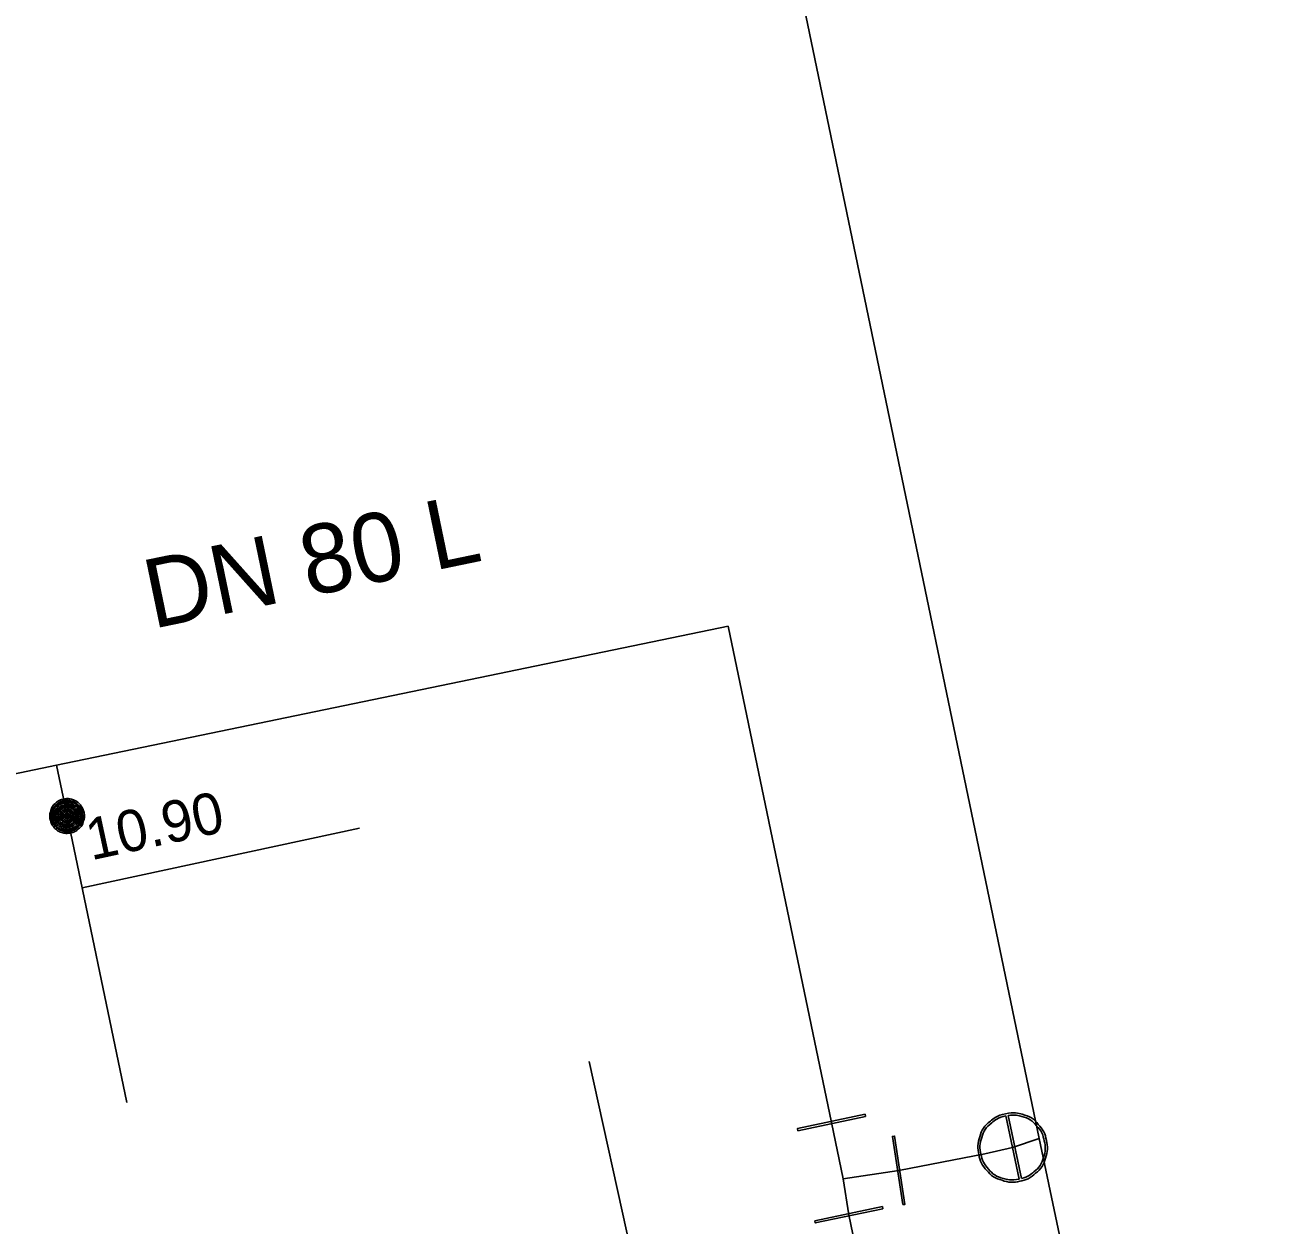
# Model space of a CAD drawing. Extents: x -820257 to -819974, y -1070894 to -1070484.
# Drawn here: x -820221.68 to -820185.49, y -1070586.44 to -1070551.67 of the extents above; entities that cross this region are included whole.
import ezdxf

# ---------------------------------------------------------------- set-up
doc = ezdxf.new("R2010")
doc.units = 0
for name, color, linetype in [('Oměrka vodovodu', 7, 'Continuous'), ('Oměrka-text', 7, 'Continuous'), ('Pás-šoupě', 7, 'Continuous'), ('Přípojka vodovodu', 7, 'Continuous'), ('Přípojkový uzávěr', 7, 'Continuous'), ('Roz-řad', 7, 'Continuous'), ('Roz-řad-popis základní', 7, 'Continuous'), ('Řad-šoupě', 7, 'Continuous')]:
    doc.layers.add(name, color=color, linetype=linetype)

msp = doc.modelspace()

# ---------------------------------------------------------------- linework, layer by layer
at = {"layer": 'Oměrka vodovodu'}
for p, q in [((-820220.023, -1070576.676), (-820211.991, -1070574.942)), ((-820199.277, -1070609.167), (-820205.332, -1070581.705))]:
    msp.add_line(p, q, dxfattribs=at)
at = {"layer": 'Pás-šoupě'}
for points in [[(-820192.875, -1070585.113), (-820193.262, -1070583.278)], [(-820193.2, -1070583.267), (-820192.814, -1070585.098)]]:
    msp.add_lwpolyline(points, dxfattribs=at)
for points in [[(-820193.274, -1070583.217), (-820193.027, -1070583.165), (-820192.767, -1070583.241), (-820192.506, -1070583.318), (-820192.324, -1070583.526), (-820192.142, -1070583.733), (-820192.088, -1070583.989), (-820192.034, -1070584.243), (-820192.114, -1070584.503), (-820192.194, -1070584.763), (-820192.4, -1070584.941), (-820192.606, -1070585.12), (-820192.861, -1070585.174), (-820193.114, -1070585.227), (-820193.374, -1070585.147), (-820193.635, -1070585.068), (-820193.813, -1070584.862), (-820193.991, -1070584.657), (-820194.045, -1070584.402), (-820194.099, -1070584.146), (-820194.017, -1070583.883), (-820193.935, -1070583.62), (-820193.728, -1070583.444), (-820193.521, -1070583.269), (-820193.274, -1070583.217)], [(-820192.814, -1070585.098), (-820192.609, -1070585.041), (-820192.441, -1070584.894), (-820192.248, -1070584.727), (-820192.173, -1070584.484), (-820192.098, -1070584.241), (-820192.149, -1070584.002), (-820192.2, -1070583.761), (-820192.371, -1070583.567), (-820192.542, -1070583.374), (-820192.786, -1070583.301), (-820192.998, -1070583.238), (-820193.2, -1070583.267)], [(-820193.262, -1070583.278), (-820193.492, -1070583.327), (-820193.687, -1070583.492), (-820193.882, -1070583.656), (-820193.958, -1070583.903), (-820194.034, -1070584.149), (-820193.983, -1070584.39), (-820193.933, -1070584.628), (-820193.766, -1070584.82), (-820193.599, -1070585.012), (-820193.355, -1070585.087), (-820193.112, -1070585.163), (-820192.875, -1070585.113)]]:
    msp.add_open_spline(points, degree=3, dxfattribs=at)
at = {"layer": 'Přípojka vodovodu'}
msp.add_lwpolyline([(-820220.764, -1070573.123), (-820220.458, -1070574.591), (-820218.725, -1070582.897)], dxfattribs=at)
at = {"layer": 'Přípojkový uzávěr'}
for points in [[(-820219.968, -1070574.489), (-820219.942, -1070574.612), (-820219.981, -1070574.742), (-820220.02, -1070574.873), (-820220.124, -1070574.963), (-820220.228, -1070575.054), (-820220.356, -1070575.081), (-820220.483, -1070575.107), (-820220.613, -1070575.067), (-820220.743, -1070575.027), (-820220.832, -1070574.924), (-820220.92, -1070574.821), (-820220.947, -1070574.693), (-820220.973, -1070574.566), (-820220.933, -1070574.436), (-820220.893, -1070574.306), (-820220.79, -1070574.217), (-820220.687, -1070574.129), (-820220.56, -1070574.102), (-820220.432, -1070574.075), (-820220.3, -1070574.116), (-820220.169, -1070574.158), (-820220.081, -1070574.261), (-820219.994, -1070574.365), (-820219.968, -1070574.489)], [(-820220.014, -1070574.498), (-820220.037, -1070574.386), (-820220.117, -1070574.292), (-820220.196, -1070574.198), (-820220.315, -1070574.161), (-820220.434, -1070574.124), (-820220.55, -1070574.148), (-820220.666, -1070574.172), (-820220.759, -1070574.252), (-820220.852, -1070574.333), (-820220.889, -1070574.451), (-820220.925, -1070574.569), (-820220.901, -1070574.683), (-820220.877, -1070574.799), (-820220.796, -1070574.893), (-820220.716, -1070574.986), (-820220.598, -1070575.023), (-820220.481, -1070575.059), (-820220.365, -1070575.035), (-820220.249, -1070575.011), (-820220.155, -1070574.928), (-820220.061, -1070574.846), (-820220.026, -1070574.728), (-820219.991, -1070574.61), (-820220.014, -1070574.498)], [(-820220.047, -1070574.505), (-820220.026, -1070574.609), (-820220.058, -1070574.718), (-820220.091, -1070574.827), (-820220.178, -1070574.903), (-820220.265, -1070574.979), (-820220.372, -1070575.002), (-820220.479, -1070575.024), (-820220.588, -1070574.99), (-820220.696, -1070574.957), (-820220.771, -1070574.87), (-820220.845, -1070574.784), (-820220.868, -1070574.676), (-820220.89, -1070574.57), (-820220.856, -1070574.461), (-820220.823, -1070574.352), (-820220.736, -1070574.278), (-820220.65, -1070574.204), (-820220.543, -1070574.181), (-820220.436, -1070574.159), (-820220.326, -1070574.193), (-820220.216, -1070574.228), (-820220.142, -1070574.315), (-820220.069, -1070574.402), (-820220.047, -1070574.505)], [(-820220.091, -1070574.514), (-820220.122, -1070574.361), (-820220.252, -1070574.277), (-820220.382, -1070574.193), (-820220.534, -1070574.224), (-820220.686, -1070574.256), (-820220.771, -1070574.386), (-820220.856, -1070574.516), (-820220.825, -1070574.667), (-820220.793, -1070574.82), (-820220.663, -1070574.905), (-820220.533, -1070574.99), (-820220.381, -1070574.959), (-820220.229, -1070574.927), (-820220.144, -1070574.797), (-820220.058, -1070574.668), (-820220.091, -1070574.514)], [(-820220.135, -1070574.523), (-820220.107, -1070574.658), (-820220.182, -1070574.771), (-820220.256, -1070574.884), (-820220.39, -1070574.911), (-820220.523, -1070574.939), (-820220.637, -1070574.865), (-820220.75, -1070574.791), (-820220.778, -1070574.657), (-820220.806, -1070574.523), (-820220.731, -1070574.41), (-820220.657, -1070574.297), (-820220.524, -1070574.269), (-820220.39, -1070574.241), (-820220.277, -1070574.315), (-820220.163, -1070574.389), (-820220.135, -1070574.523)], [(-820220.174, -1070574.531), (-820220.199, -1070574.414), (-820220.299, -1070574.348), (-820220.398, -1070574.283), (-820220.516, -1070574.308), (-820220.633, -1070574.332), (-820220.698, -1070574.432), (-820220.764, -1070574.532), (-820220.739, -1070574.649), (-820220.715, -1070574.766), (-820220.615, -1070574.832), (-820220.515, -1070574.897), (-820220.398, -1070574.873), (-820220.281, -1070574.848), (-820220.215, -1070574.749), (-820220.15, -1070574.649), (-820220.174, -1070574.531)], [(-820220.213, -1070574.54), (-820220.191, -1070574.643), (-820220.248, -1070574.729), (-820220.305, -1070574.815), (-820220.407, -1070574.836), (-820220.508, -1070574.857), (-820220.595, -1070574.801), (-820220.681, -1070574.744), (-820220.702, -1070574.642), (-820220.723, -1070574.541), (-820220.667, -1070574.454), (-820220.61, -1070574.368), (-820220.509, -1070574.347), (-820220.407, -1070574.325), (-820220.321, -1070574.382), (-820220.234, -1070574.438), (-820220.213, -1070574.54)], [(-820220.258, -1070574.549), (-820220.275, -1070574.467), (-820220.346, -1070574.421), (-820220.416, -1070574.375), (-820220.499, -1070574.392), (-820220.581, -1070574.409), (-820220.627, -1070574.479), (-820220.673, -1070574.55), (-820220.656, -1070574.632), (-820220.639, -1070574.714), (-820220.569, -1070574.761), (-820220.498, -1070574.807), (-820220.416, -1070574.79), (-820220.333, -1070574.772), (-820220.287, -1070574.702), (-820220.241, -1070574.632), (-820220.258, -1070574.549)], [(-820220.292, -1070574.556), (-820220.278, -1070574.625), (-820220.316, -1070574.683), (-820220.354, -1070574.741), (-820220.423, -1070574.756), (-820220.491, -1070574.77), (-820220.55, -1070574.732), (-820220.608, -1070574.694), (-820220.622, -1070574.625), (-820220.636, -1070574.556), (-820220.598, -1070574.498), (-820220.56, -1070574.44), (-820220.491, -1070574.426), (-820220.423, -1070574.412), (-820220.365, -1070574.45), (-820220.307, -1070574.488), (-820220.292, -1070574.556)], [(-820220.335, -1070574.565), (-820220.346, -1070574.515), (-820220.389, -1070574.487), (-820220.432, -1070574.458), (-820220.483, -1070574.469), (-820220.534, -1070574.48), (-820220.562, -1070574.523), (-820220.59, -1070574.566), (-820220.58, -1070574.616), (-820220.569, -1070574.668), (-820220.526, -1070574.696), (-820220.483, -1070574.724), (-820220.432, -1070574.714), (-820220.381, -1070574.703), (-820220.353, -1070574.66), (-820220.324, -1070574.617), (-820220.335, -1070574.565)], [(-820220.381, -1070574.575), (-820220.374, -1070574.607), (-820220.392, -1070574.634), (-820220.409, -1070574.661), (-820220.442, -1070574.667), (-820220.473, -1070574.674), (-820220.5, -1070574.657), (-820220.527, -1070574.639), (-820220.534, -1070574.607), (-820220.541, -1070574.575), (-820220.523, -1070574.548), (-820220.505, -1070574.521), (-820220.473, -1070574.514), (-820220.441, -1070574.508), (-820220.414, -1070574.525), (-820220.388, -1070574.543), (-820220.381, -1070574.575)], [(-820220.412, -1070574.581), (-820220.416, -1070574.562), (-820220.432, -1070574.552), (-820220.448, -1070574.541), (-820220.467, -1070574.545), (-820220.486, -1070574.549), (-820220.497, -1070574.565), (-820220.507, -1070574.581), (-820220.503, -1070574.6), (-820220.499, -1070574.62), (-820220.483, -1070574.63), (-820220.467, -1070574.641), (-820220.448, -1070574.637), (-820220.428, -1070574.633), (-820220.418, -1070574.617), (-820220.408, -1070574.601), (-820220.412, -1070574.581)]]:
    msp.add_open_spline(points, degree=3, dxfattribs=at)
at = {"layer": 'Roz-řad'}
for p, q in [((-820198.316, -1070583.473), (-820197.972, -1070585.102)), ((-820193.067, -1070584.196), (-820192.294, -1070583.934)), ((-820197.972, -1070585.102), (-820196.367, -1070584.859)), ((-820197.972, -1070585.102), (-820197.811, -1070586.146))]:
    msp.add_line(p, q, dxfattribs=at)
for points in [[(-820192.294, -1070583.934), (-820204.367, -1070525.825), (-820206.422, -1070517.249), (-820209.898, -1070501.039), (-820209.965, -1070500.833), (-820212.767, -1070486.628), (-820213.283, -1070484.403)], [(-820229.04, -1070574.846), (-820220.764, -1070573.123), (-820201.308, -1070569.092), (-820198.316, -1070583.473)], [(-820192.294, -1070583.934), (-820183.322, -1070626.593), (-820174.41, -1070657.75)], [(-820196.367, -1070584.859), (-820193.872, -1070584.38), (-820193.067, -1070584.196)], [(-820197.811, -1070586.146), (-820193.283, -1070608.01), (-820191.043, -1070618.489), (-820190.615, -1070620.124), (-820190.84, -1070620.738)]]:
    msp.add_lwpolyline(points, dxfattribs=at)
at = {"layer": 'Řad-šoupě'}
for points in [[(-820197.33, -1070583.296), (-820199.287, -1070583.709), (-820199.3, -1070583.648), (-820197.343, -1070583.234), (-820197.33, -1070583.296)], [(-820196.248, -1070585.852), (-820196.548, -1070583.875), (-820196.486, -1070583.866), (-820196.186, -1070585.843), (-820196.248, -1070585.852)], [(-820196.825, -1070585.969), (-820198.782, -1070586.382), (-820198.795, -1070586.321), (-820196.838, -1070585.907), (-820196.825, -1070585.969)]]:
    msp.add_lwpolyline(points, dxfattribs=at)

# ---------------------------------------------------------------- texts
at = {"layer": 'Oměrka-text'}
msp.add_text('10.90', height=1.2, rotation=12.1824, dxfattribs=at).set_placement((-820219.762, -1070575.879))
at = {"layer": 'Roz-řad-popis základní'}
msp.add_text('DN 80 L', height=2, rotation=11.7052, dxfattribs=at).set_placement((-820217.981, -1070569.173))

doc.saveas('drawing.dxf')
